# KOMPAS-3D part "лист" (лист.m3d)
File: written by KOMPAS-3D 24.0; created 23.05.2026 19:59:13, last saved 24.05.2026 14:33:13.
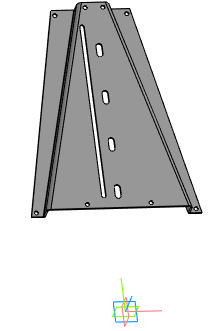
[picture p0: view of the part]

Document properties: Автор: R2D2; Полное имя файла: E:\Работа\Зайцев\GVKR1331M-1W-Fb-2P Задвижка шиберная с выдвижным штоком DN.ru Ду50-300 Ру16-10-6 с пневмоприводом\исходные материалы\DN300\лист.m3d

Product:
- Part/product: лист
    Масса: 5.441535
    Раздел спецификации: Прочие изделия
    Примечание: D040-08800

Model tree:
1. Эскиз:6  (with: Грань.Элемент выдавливания:15, Ребро.Элемент выдавливания:15)
2. Эскиз:7  (with: Грань.Элемент выдавливания:6, Ребро.Элемент выдавливания:6, Ребро.Элемент выдавливания:12)
3. Линейчатая обечайка:1
     Расстояние 1 = 10; Толщина листового тела = 4; Коэффициент = 0.5
4. Сгиб(1) - Линейчатая обечайка:1
     Радиус сгиба = 5; Коэффициент = 0.5; Величина сгиба = 5
5. Сгиб(2) - Линейчатая обечайка:1
     Радиус сгиба = 5; Коэффициент = 0.5; Величина сгиба = 5
6. Сгиб(3) - Линейчатая обечайка:1
     Радиус сгиба = 5; Коэффициент = 0.5; Величина сгиба = 5
7. Сгиб(4) - Линейчатая обечайка:1
     Радиус сгиба = 5; Коэффициент = 0.5; Величина сгиба = 5; Зазор = 1; Угол = 360; Параметр U, % = 100; Длина = 149
8. Эскиз:8  (with: Грань.Линейчатая обечайка:1, Ребро.Линейчатая обечайка:1)
9. Отверстие в листовом теле:1  (with: Грань.Линейчатая обечайка:1, Ребро.Линейчатая обечайка:1)
     Глубина выреза = 10; Расстояние 1 = 10; Расстояние 2 = 10
10. Отверстие в листовом теле:2  (with: Грань.Линейчатая обечайка:1, Ребро.Линейчатая обечайка:1)
     Глубина выреза = 10; Расстояние 1 = -80; Расстояние 2 = 10
11. Отверстие в листовом теле:3  (with: Грань.Линейчатая обечайка:1, Ребро.Линейчатая обечайка:1)
     Глубина выреза = 10; Расстояние 1 = -221.127; Расстояние 2 = 10
12. Отверстие в листовом теле:4  (with: Грань.Линейчатая обечайка:1, Ребро.Линейчатая обечайка:1)
     Глубина выреза = 10; Расстояние 1 = -16.4093; Расстояние 2 = 10
13. Отверстие в листовом теле:5  (with: Грань.Линейчатая обечайка:1, Ребро.Линейчатая обечайка:1)
     Глубина выреза = 10; Расстояние 1 = 10; Расстояние 2 = 496
14. Отверстие в листовом теле:6  (with: Грань.Линейчатая обечайка:1, Ребро.Линейчатая обечайка:1)
     Глубина выреза = 10; Расстояние 1 = -10; Расстояние 2 = 496
15. Отверстие в листовом теле:7  (with: Грань.Линейчатая обечайка:1, Ребро.Линейчатая обечайка:1)
     Глубина выреза = 10; Расстояние 1 = -49.1771; Расстояние 2 = 496
16. Отверстие в листовом теле:8  (with: Грань.Линейчатая обечайка:1, Ребро.Линейчатая обечайка:1)
     Глубина выреза = 10; Расстояние 1 = -40.189; Расстояние 2 = 496
17. Эскиз:9  (with: Грань.Линейчатая обечайка:1, Ребро.Линейчатая обечайка:1)
18. Эскиз:10  (with: Грань.Линейчатая обечайка:1, Ребро.Линейчатая обечайка:1)
19. Вырез в листовом теле:1
     Глубина выреза = 10
20. Вырез в листовом теле:2
     Глубина выреза = 10

Expressions: 2*h
Referenced files in E:\Работа\Зайцев\GVKR1331M-1W-Fb-2P Задвижка шиберная с выдвижным штоком DN.ru Ду50-300 Ру16-10-6 с пневмоприводом\исходные материалы\DN300\: GVKR1331M-1W-Fb-2P Задвижка шиберная с выдвижным штоком DN.ru Ду300 Ру6.a3d
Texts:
  Шаг 2
  Шаг 1
  Затвор дисковый DN.ru Ду Ру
